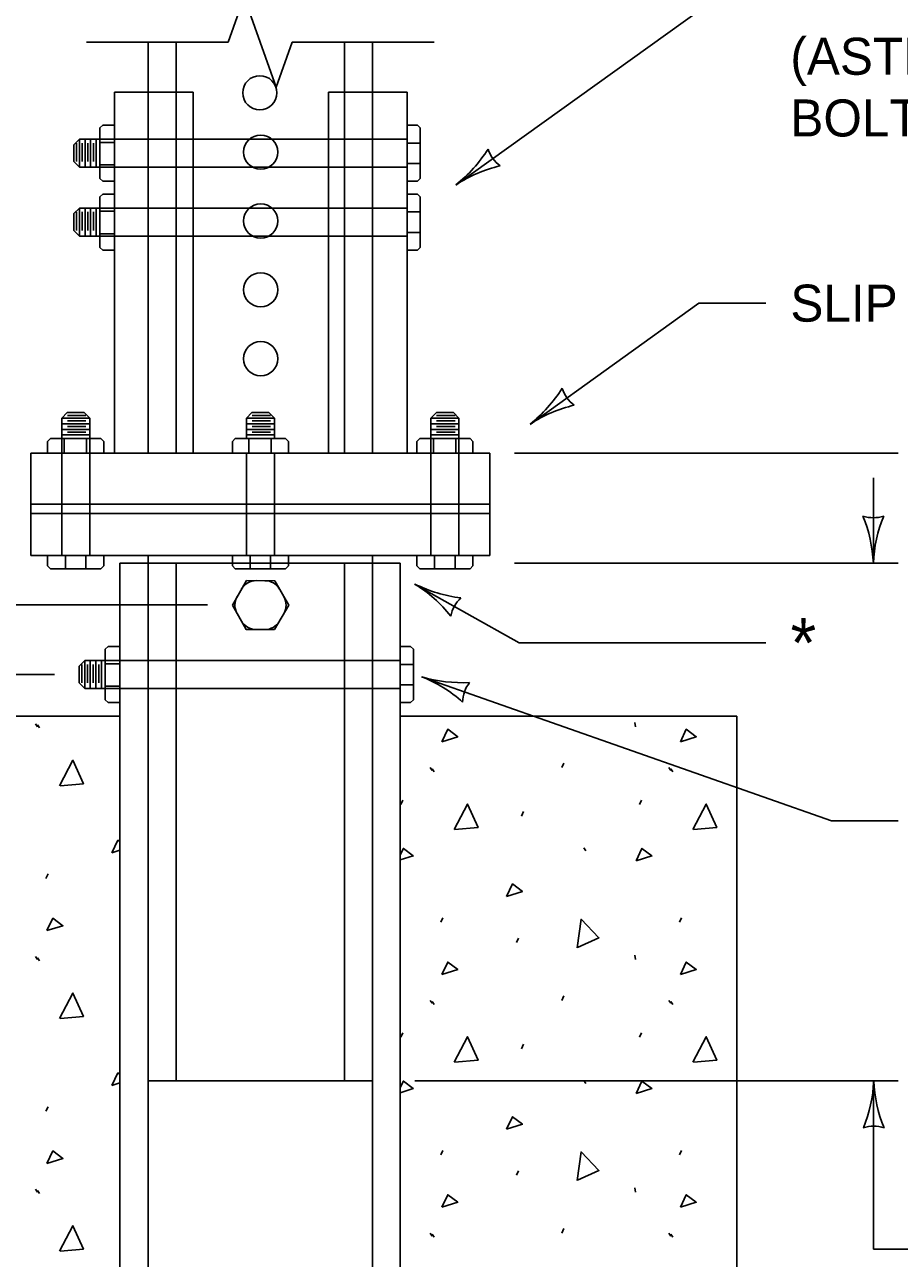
# Model space of a CAD drawing. Extents: x 49940 to 50043, y 49986 to 50011.
# Drawn here: x 50033.246 to 50034.663, y 49992.517 to 49994.516 of the extents above; entities that cross this region are included whole.
import ezdxf

# ---------------------------------------------------------------- set-up
doc = ezdxf.new("R2010")
doc.units = 0
for name, color, linetype in [('Level 1', 7, 'Continuous'), ('Level 2', 7, 'Continuous'), ('Level 3', 7, 'Continuous'), ('Level 4', 7, 'Continuous'), ('Level 6', 7, 'Continuous')]:
    doc.layers.add(name, color=color, linetype=linetype)

msp = doc.modelspace()

# ---------------------------------------------------------------- linework, layer by layer
at = {"layer": 'Level 1'}
for p, q in [((50033.3912, 49994.4061), (50033.3912, 49993.8213)), ((50033.3912, 49994.4061), (50033.5184, 49994.4061)), ((50033.5184, 49994.4061), (50033.5184, 49993.8213)), ((50033.738, 49994.4061), (50033.738, 49993.8213)), ((50033.8652, 49994.4061), (50033.738, 49994.4061)), ((50033.8652, 49994.4061), (50033.8652, 49993.8213)), ((50033.3675, 49994.3484), (50033.3721, 49994.3529)), ((50033.3675, 49994.2666), (50033.3675, 49994.3484)), ((50033.3912, 49994.3529), (50033.3721, 49994.3529)), ((50033.8819, 49994.3529), (50033.8652, 49994.3529)), ((50033.8864, 49994.3484), (50033.8819, 49994.3529)), ((50033.8864, 49994.2666), (50033.8864, 49994.3484)), ((50033.3253, 49994.3211), (50033.3344, 49994.3302)), ((50033.3253, 49994.2939), (50033.3253, 49994.3211)), ((50033.3298, 49994.294), (50033.3298, 49994.3239)), ((50033.3675, 49994.3302), (50033.3344, 49994.3302)), ((50033.3344, 49994.2848), (50033.3344, 49994.3302)), ((50033.3389, 49994.294), (50033.3389, 49994.3239)), ((50033.3435, 49994.2848), (50033.3435, 49994.3302)), ((50033.348, 49994.294), (50033.348, 49994.3239)), ((50033.3525, 49994.2848), (50033.3525, 49994.3302)), ((50033.3571, 49994.294), (50033.3571, 49994.3239)), ((50033.3616, 49994.2848), (50033.3616, 49994.3302)), ((50033.3675, 49994.3249), (50033.3898, 49994.3249)), ((50033.8864, 49994.3239), (50033.8658, 49994.3239)), ((50033.3253, 49994.2939), (50033.3344, 49994.2848)), ((50033.3675, 49994.2848), (50033.3344, 49994.2848)), ((50033.3675, 49994.2887), (50033.3898, 49994.2887)), ((50033.8864, 49994.2908), (50033.8658, 49994.2908)), ((50033.3675, 49994.2666), (50033.3721, 49994.262)), ((50033.3912, 49994.262), (50033.3721, 49994.262)), ((50033.8819, 49994.262), (50033.8652, 49994.262)), ((50033.8819, 49994.262), (50033.8864, 49994.2666)), ((50033.3675, 49994.2367), (50033.3721, 49994.2413)), ((50033.3912, 49994.2413), (50033.3721, 49994.2413)), ((50033.8819, 49994.2413), (50033.8652, 49994.2413)), ((50033.8864, 49994.2367), (50033.8819, 49994.2413)), ((50033.3675, 49994.1549), (50033.3675, 49994.2367)), ((50033.8864, 49994.1549), (50033.8864, 49994.2367)), ((50033.3253, 49994.2095), (50033.3344, 49994.2186)), ((50033.3253, 49994.1822), (50033.3253, 49994.2095)), ((50033.3298, 49994.1824), (50033.3298, 49994.2122)), ((50033.3675, 49994.2186), (50033.3344, 49994.2186)), ((50033.3344, 49994.1731), (50033.3344, 49994.2186)), ((50033.3389, 49994.1824), (50033.3389, 49994.2122)), ((50033.3435, 49994.1731), (50033.3435, 49994.2186)), ((50033.348, 49994.1824), (50033.348, 49994.2122)), ((50033.3525, 49994.1731), (50033.3525, 49994.2186)), ((50033.3571, 49994.1824), (50033.3571, 49994.2122)), ((50033.3616, 49994.1731), (50033.3616, 49994.2186)), ((50033.3675, 49994.2133), (50033.3898, 49994.2133)), ((50033.8864, 49994.2122), (50033.8658, 49994.2122)), ((50033.3253, 49994.1822), (50033.3344, 49994.1731)), ((50033.3675, 49994.1731), (50033.3344, 49994.1731)), ((50033.3675, 49994.177), (50033.3898, 49994.177)), ((50033.8864, 49994.1792), (50033.8658, 49994.1792)), ((50033.3675, 49994.1549), (50033.3721, 49994.1504)), ((50033.3912, 49994.1504), (50033.3721, 49994.1504)), ((50033.8819, 49994.1504), (50033.8652, 49994.1504)), ((50033.8819, 49994.1504), (50033.8864, 49994.1549)), ((50033.3147, 49993.8872), (50033.3056, 49993.8781)), ((50033.3147, 49993.8872), (50033.3419, 49993.8872)), ((50033.3148, 49993.8827), (50033.3447, 49993.8827)), ((50033.3419, 49993.8872), (50033.351, 49993.8781)), ((50033.6139, 49993.8872), (50033.6048, 49993.8781)), ((50033.6139, 49993.8872), (50033.6412, 49993.8872)), ((50033.614, 49993.8827), (50033.6439, 49993.8827)), ((50033.6412, 49993.8872), (50033.6502, 49993.8781)), ((50033.9129, 49993.8872), (50033.9039, 49993.8781)), ((50033.9129, 49993.8872), (50033.9402, 49993.8872)), ((50033.9131, 49993.8827), (50033.9429, 49993.8827)), ((50033.9402, 49993.8872), (50033.9493, 49993.8781)), ((50033.3056, 49993.845), (50033.3056, 49993.8781)), ((50033.3056, 49993.8781), (50033.351, 49993.8781)), ((50033.3056, 49993.869), (50033.351, 49993.869)), ((50033.3148, 49993.8736), (50033.3447, 49993.8736)), ((50033.3148, 49993.8645), (50033.3447, 49993.8645)), ((50033.351, 49993.845), (50033.351, 49993.8781)), ((50033.6048, 49993.845), (50033.6048, 49993.8781)), ((50033.6048, 49993.8781), (50033.6502, 49993.8781)), ((50033.6048, 49993.869), (50033.6502, 49993.869)), ((50033.614, 49993.8736), (50033.6439, 49993.8736)), ((50033.614, 49993.8645), (50033.6439, 49993.8645)), ((50033.6502, 49993.845), (50033.6502, 49993.8781)), ((50033.9039, 49993.845), (50033.9039, 49993.8781)), ((50033.9039, 49993.8781), (50033.9493, 49993.8781)), ((50033.9039, 49993.869), (50033.9493, 49993.869)), ((50033.9131, 49993.8736), (50033.9429, 49993.8736)), ((50033.9131, 49993.8645), (50033.9429, 49993.8645)), ((50033.9493, 49993.845), (50033.9493, 49993.8781)), ((50033.2874, 49993.845), (50033.2829, 49993.8404)), ((50033.2874, 49993.845), (50033.3692, 49993.845)), ((50033.3056, 49993.86), (50033.351, 49993.86)), ((50033.3056, 49993.8509), (50033.351, 49993.8509)), ((50033.3095, 49993.845), (50033.3095, 49993.8227)), ((50033.3148, 49993.8554), (50033.3447, 49993.8554)), ((50033.3457, 49993.845), (50033.3457, 49993.8227)), ((50033.3692, 49993.845), (50033.3738, 49993.8404)), ((50033.5866, 49993.845), (50033.5821, 49993.8404)), ((50033.5866, 49993.845), (50033.6684, 49993.845)), ((50033.6048, 49993.86), (50033.6502, 49993.86)), ((50033.6048, 49993.8509), (50033.6502, 49993.8509)), ((50033.6087, 49993.845), (50033.6087, 49993.8227)), ((50033.614, 49993.8554), (50033.6439, 49993.8554)), ((50033.6449, 49993.845), (50033.6449, 49993.8227)), ((50033.6684, 49993.845), (50033.673, 49993.8404)), ((50033.8857, 49993.845), (50033.8811, 49993.8404)), ((50033.8857, 49993.845), (50033.9675, 49993.845)), ((50033.9039, 49993.86), (50033.9493, 49993.86)), ((50033.9039, 49993.8509), (50033.9493, 49993.8509)), ((50033.9078, 49993.845), (50033.9078, 49993.8227)), ((50033.9131, 49993.8554), (50033.9429, 49993.8554)), ((50033.944, 49993.845), (50033.944, 49993.8227)), ((50033.9675, 49993.845), (50033.972, 49993.8404)), ((50033.2556, 49993.6554), (50033.2556, 49993.8213)), ((50033.2556, 49993.8213), (50033.6048, 49993.8213)), ((50033.2829, 49993.8213), (50033.2829, 49993.8404)), ((50033.3738, 49993.8213), (50033.3738, 49993.8404)), ((50033.5821, 49993.8213), (50033.5821, 49993.8404)), ((50033.6048, 49993.6554), (50033.6048, 49993.8213)), ((50033.6048, 49993.8213), (50033.6502, 49993.8213)), ((50033.6502, 49993.6554), (50033.6502, 49993.8213)), ((50033.6502, 49993.8213), (50033.9993, 49993.8213)), ((50033.673, 49993.8213), (50033.673, 49993.8404)), ((50033.8811, 49993.8213), (50033.8811, 49993.8404)), ((50033.972, 49993.8213), (50033.972, 49993.8404)), ((50033.9993, 49993.6554), (50033.9993, 49993.8213)), ((50033.2556, 49993.7389), (50033.9993, 49993.7389)), ((50033.2556, 49993.7239), (50033.9993, 49993.7239)), ((50033.2556, 49993.6554), (50033.6048, 49993.6554)), ((50033.2829, 49993.6388), (50033.2829, 49993.6554)), ((50033.3116, 49993.6342), (50033.3116, 49993.6548)), ((50033.3447, 49993.6342), (50033.3447, 49993.6548)), ((50033.3738, 49993.6388), (50033.3738, 49993.6554)), ((50033.8542, 49993.6432), (50033.3997, 49993.6432)), ((50033.3997, 49993.6432), (50033.3997, 49990.8091)), ((50033.4457, 49993.6554), (50033.4457, 49993.6432)), ((50033.5821, 49993.6388), (50033.5821, 49993.6554)), ((50033.6048, 49993.6554), (50033.6502, 49993.6554)), ((50033.6109, 49993.6342), (50033.6109, 49993.6548)), ((50033.6439, 49993.6342), (50033.6439, 49993.6548)), ((50033.6502, 49993.6554), (50033.9993, 49993.6554)), ((50033.673, 49993.6388), (50033.673, 49993.6554)), ((50033.8093, 49993.6554), (50033.8093, 49993.6432)), ((50033.8542, 49990.8091), (50033.8542, 49993.6432)), ((50033.8811, 49993.6388), (50033.8811, 49993.6554)), ((50033.9099, 49993.6342), (50033.9099, 49993.6548)), ((50033.9429, 49993.6342), (50033.9429, 49993.6548)), ((50033.972, 49993.6388), (50033.972, 49993.6554)), ((50033.2829, 49993.6388), (50033.2874, 49993.6342)), ((50033.2874, 49993.6342), (50033.3692, 49993.6342)), ((50033.3692, 49993.6342), (50033.3738, 49993.6388)), ((50033.5821, 49993.6388), (50033.5866, 49993.6342)), ((50033.5866, 49993.6342), (50033.6684, 49993.6342)), ((50033.6684, 49993.6342), (50033.673, 49993.6388)), ((50033.8811, 49993.6388), (50033.8857, 49993.6342)), ((50033.8857, 49993.6342), (50033.9675, 49993.6342)), ((50033.9675, 49993.6342), (50033.972, 49993.6388)), ((50033.3762, 49993.5036), (50033.3807, 49993.5082)), ((50033.3762, 49993.4218), (50033.3762, 49993.5036)), ((50033.3997, 49993.5082), (50033.3807, 49993.5082)), ((50033.8708, 49993.5082), (50033.8542, 49993.5082)), ((50033.8542, 49993.5082), (50033.8542, 49993.4173)), ((50033.8754, 49993.5036), (50033.8708, 49993.5082)), ((50033.8754, 49993.4218), (50033.8754, 49993.5036)), ((50033.3338, 49993.4764), (50033.3429, 49993.4855)), ((50033.3762, 49993.4855), (50033.3429, 49993.4855)), ((50033.3429, 49993.44), (50033.3429, 49993.4855)), ((50033.3519, 49993.44), (50033.3519, 49993.4855)), ((50033.361, 49993.44), (50033.361, 49993.4855)), ((50033.3701, 49993.44), (50033.3701, 49993.4855)), ((50033.8542, 49993.4855), (50033.8473, 49993.4855)), ((50033.3338, 49993.4491), (50033.3338, 49993.4764)), ((50033.3383, 49993.4492), (50033.3383, 49993.4791)), ((50033.3474, 49993.4492), (50033.3474, 49993.4791)), ((50033.3565, 49993.4492), (50033.3565, 49993.4791)), ((50033.3656, 49993.4492), (50033.3656, 49993.4791)), ((50033.3762, 49993.4801), (50033.3997, 49993.4801)), ((50033.8754, 49993.4791), (50033.8548, 49993.4791)), ((50033.3338, 49993.4491), (50033.3429, 49993.44)), ((50033.3762, 49993.4439), (50033.3997, 49993.4439)), ((50033.8754, 49993.4461), (50033.8548, 49993.4461)), ((50033.3762, 49993.44), (50033.3429, 49993.44)), ((50033.3762, 49993.4218), (50033.3807, 49993.4173)), ((50033.8708, 49993.4173), (50033.8754, 49993.4218)), ((50033.3997, 49993.4173), (50033.3807, 49993.4173)), ((50033.8708, 49993.4173), (50033.8542, 49993.4173)), ((50033.3997, 49993.3952), (50032.8543, 49993.3952)), ((50033.2632, 49993.3829), (50033.2665, 49993.378)), ((50034.3996, 49993.3952), (50033.8542, 49993.3952)), ((50034.2343, 49993.3853), (50034.2352, 49993.378)), ((50034.3996, 49990.6682), (50034.3996, 49993.3952)), ((50033.2665, 49993.3811), (50033.2697, 49993.3762)), ((50033.9028, 49993.312), (50033.906, 49993.3071)), ((50033.906, 49993.31), (50033.9092, 49993.3052)), ((50034.1158, 49993.312), (50034.1191, 49993.3193)), ((50034.2894, 49993.312), (50034.2926, 49993.3071)), ((50034.2926, 49993.31), (50034.2959, 49993.3052)), ((50033.8551, 49993.2521), (50033.8584, 49993.2594)), ((50034.2419, 49993.2521), (50034.245, 49993.2594)), ((50034.0505, 49993.2335), (50034.0537, 49993.2408)), ((50034.1514, 49993.1818), (50034.1546, 49993.177)), ((50033.2801, 49993.1325), (50033.2835, 49993.1397)), ((50033.9198, 49993.0616), (50033.9229, 49993.0688)), ((50034.3064, 49993.0616), (50034.3096, 49993.0688)), ((50034.0423, 49993.0285), (50034.0457, 49993.0358)), ((50033.2632, 49993.0058), (50033.2665, 49993.001)), ((50033.2665, 49993.004), (50033.2697, 49992.9991)), ((50034.2343, 49993.0082), (50034.2352, 49993.001)), ((50034.1158, 49992.9349), (50034.1191, 49992.9422)), ((50033.9028, 49992.9349), (50033.906, 49992.9301)), ((50033.906, 49992.9331), (50033.9092, 49992.9282)), ((50034.2894, 49992.9349), (50034.2926, 49992.9301)), ((50034.2926, 49992.9331), (50034.2959, 49992.9282)), ((50033.8551, 49992.8751), (50033.8584, 49992.8823)), ((50034.2419, 49992.8751), (50034.245, 49992.8823)), ((50034.0505, 49992.8564), (50034.0537, 49992.8637)), ((50034.1514, 49992.8048), (50034.1546, 49992.7999)), ((50033.2801, 49992.7555), (50033.2835, 49992.7626)), ((50033.9198, 49992.6845), (50033.9229, 49992.6917)), ((50034.3064, 49992.6845), (50034.3096, 49992.6917)), ((50034.0423, 49992.6514), (50034.0457, 49992.6587)), ((50033.2632, 49992.6287), (50033.2665, 49992.6239)), ((50033.2665, 49992.6269), (50033.2697, 49992.6221)), ((50034.2343, 49992.6311), (50034.2352, 49992.6239)), ((50034.1158, 49992.5578), (50034.1191, 49992.5651)), ((50033.9028, 49992.5578), (50033.906, 49992.553)), ((50033.906, 49992.556), (50033.9092, 49992.5512)), ((50034.2894, 49992.5578), (50034.2926, 49992.553)), ((50034.2926, 49992.556), (50034.2959, 49992.5512))]:
    msp.add_line(p, q, dxfattribs=at)
for points in [[(50033.4457, 49994.4875), (50033.4457, 49994.4061)], [(50033.809, 49994.4061), (50033.809, 49994.4875)], [(50033.9213, 49993.3539), (50033.931, 49993.3741), (50033.9472, 49993.362), (50033.9213, 49993.3539)], [(50034.3081, 49993.3539), (50034.3176, 49993.3741), (50034.3338, 49993.362), (50034.3081, 49993.3539)], [(50033.3019, 49993.2826), (50033.3238, 49993.3238), (50033.3407, 49993.2859), (50033.3029, 49993.2826)], [(50033.9414, 49993.2117), (50033.9632, 49993.2529), (50033.9802, 49993.215), (50033.9423, 49993.2117)], [(50034.3282, 49993.2117), (50034.35, 49993.2529), (50034.3668, 49993.215), (50034.329, 49993.2117)], [(50033.3869, 49993.1741), (50033.3966, 49993.1943), (50033.3997, 49993.192)], [(50033.3997, 49993.1781), (50033.3869, 49993.1741)], [(50033.8542, 49993.1706), (50033.8592, 49993.1811), (50033.8752, 49993.169), (50033.8542, 49993.1623)], [(50034.2361, 49993.1609), (50034.2458, 49993.1811), (50034.262, 49993.169), (50034.2361, 49993.1609)], [(50034.0264, 49993.1032), (50034.0361, 49993.1234), (50034.0522, 49993.1112), (50034.0264, 49993.1032)], [(50033.2818, 49993.0478), (50033.2915, 49993.0679), (50033.3077, 49993.0558), (50033.2818, 49993.0478)], [(50034.1406, 49993.0202), (50034.147, 49993.0663), (50034.1759, 49993.0364), (50034.1414, 49993.0203)], [(50033.9213, 49992.9769), (50033.931, 49992.997), (50033.9472, 49992.9849), (50033.9213, 49992.9769)], [(50034.3081, 49992.9769), (50034.3176, 49992.997), (50034.3338, 49992.9849), (50034.3081, 49992.9769)], [(50033.3019, 49992.9057), (50033.3238, 49992.9467), (50033.3407, 49992.9088), (50033.3029, 49992.9057)], [(50033.9414, 49992.8346), (50033.9632, 49992.8758), (50033.9802, 49992.8379), (50033.9423, 49992.8346)], [(50034.3282, 49992.8346), (50034.35, 49992.8758), (50034.3668, 49992.8379), (50034.329, 49992.8346)], [(50033.3869, 49992.797), (50033.3966, 49992.8172), (50033.3997, 49992.8149)], [(50033.8542, 49992.7936), (50033.8592, 49992.804), (50033.8752, 49992.7919), (50033.8542, 49992.7852)], [(50034.2361, 49992.7839), (50034.2458, 49992.804), (50034.262, 49992.7919), (50034.2361, 49992.7839)], [(50033.3997, 49992.801), (50033.3869, 49992.797)], [(50034.0264, 49992.7261), (50034.0361, 49992.7463), (50034.0522, 49992.7342), (50034.0264, 49992.7261)], [(50033.2818, 49992.6707), (50033.2915, 49992.6908), (50033.3077, 49992.6787), (50033.2818, 49992.6707)], [(50034.1406, 49992.6431), (50034.147, 49992.6892), (50034.1759, 49992.6593), (50034.1414, 49992.6434)], [(50033.9213, 49992.5998), (50033.931, 49992.6199), (50033.9472, 49992.6078), (50033.9213, 49992.5998)], [(50034.3081, 49992.5998), (50034.3176, 49992.6199), (50034.3338, 49992.6078), (50034.3081, 49992.5998)], [(50033.3019, 49992.5286), (50033.3238, 49992.5696), (50033.3407, 49992.5318), (50033.3029, 49992.5286)]]:
    msp.add_lwpolyline(points, dxfattribs=at)
msp.add_lwpolyline([(50033.5821, 49993.5754), (50033.6046, 49993.5357), (50033.6502, 49993.5356), (50033.6734, 49993.575), (50033.6507, 49993.6147), (50033.6051, 49993.615)], close=True, dxfattribs=at)
for centre in [(50033.6266, 49994.4053), (50033.6281, 49994.3092), (50033.6281, 49994.3092), (50033.6281, 49994.1977), (50033.6281, 49994.1977), (50033.6281, 49994.1977), (50033.6281, 49994.0861), (50033.6281, 49993.9745)]:
    msp.add_circle(centre, 0.0277, dxfattribs=at)
for centre, start, end in [((50033.6207, 49993.5876), 89.696, 149.6971), ((50033.6348, 49993.5875), 29.6985, 89.6961), ((50033.6135, 49993.5753), 149.6985, 209.6957), ((50033.6419, 49993.5752), 329.6973, 29.6966), ((50033.6205, 49993.563), 209.697, 269.6988), ((50033.6347, 49993.5629), 269.6962, 329.6979)]:
    msp.add_arc(centre, 0.0273, start, end, dxfattribs=at)
at = {"layer": 'Level 3'}
for p, q in [((50034.3744, 49994.5645), (50033.9444, 49994.2558)), ((50034.0645, 49993.8681), (50034.338, 49994.0645)), ((50034.338, 49994.0645), (50034.4462, 49994.0645)), ((50034.0395, 49993.8215), (50034.6609, 49993.8215)), ((50034.6209, 49993.7815), (50034.6209, 49993.6432)), ((50034.6609, 49993.6432), (50034.0395, 49993.6432)), ((50033.8775, 49993.6092), (50034.0468, 49993.5143)), ((50033.5421, 49993.5756), (50032.4723, 49993.5756)), ((50034.0468, 49993.5143), (50034.4462, 49993.5143)), ((50033.2938, 49993.4629), (50032.4723, 49993.4629)), ((50033.8888, 49993.459), (50034.5527, 49993.2255)), ((50034.5527, 49993.2255), (50034.6609, 49993.2255)), ((50033.8777, 49992.8047), (50034.6609, 49992.8047)), ((50034.6209, 49992.8047), (50034.6209, 49992.532)), ((50034.6209, 49992.532), (50034.7291, 49992.532))]:
    msp.add_line(p, q, dxfattribs=at)
for centre, radius, start, end in [((50033.7993, 49994.4385), 0.233, 308.5027, 327.7526), ((50034.0485, 49994.3309), 0.0548, 197.8142, 233.5366), ((50034.0665, 49994.0704), 0.2223, 103.1314, 123.3149), ((50033.9194, 49994.0508), 0.233, 308.5094, 327.7592), ((50034.1686, 49993.9432), 0.0548, 197.8209, 233.5433), ((50034.1866, 49993.6827), 0.2223, 103.1381, 123.3216), ((50034.6206, 49993.7716), 0.0548, 252.1388, 287.8612), ((50034.3879, 49993.6319), 0.233, 2.8273, 22.0772), ((50034.8428, 49993.6342), 0.2223, 157.456, 177.6395), ((50033.7612, 49993.4201), 0.2223, 38.1835, 58.367), ((50033.9816, 49993.818), 0.233, 243.5548, 262.8046), ((50033.9897, 49993.5467), 0.0548, 132.8663, 168.5887), ((50033.8067, 49993.2527), 0.2223, 48.0787, 68.2623), ((50033.9554, 49993.6825), 0.233, 253.45, 272.6999), ((50034.01, 49993.4167), 0.0548, 142.7616, 178.4839), ((50034.3991, 49992.8137), 0.2223, 337.456, 357.6395), ((50034.8539, 49992.816), 0.233, 182.8273, 202.0772), ((50034.6212, 49992.6763), 0.0548, 72.1388, 107.8612)]:
    msp.add_arc(centre, radius, start, end, dxfattribs=at)
at = {"layer": 'Level 4'}
for p, q in [((50033.8652, 49994.3302), (50033.3675, 49994.3302)), ((50033.8652, 49994.2848), (50033.3675, 49994.2848)), ((50033.8652, 49994.2186), (50033.3675, 49994.2186)), ((50033.8652, 49994.1731), (50033.3675, 49994.1731)), ((50033.3056, 49993.6554), (50033.3056, 49993.845)), ((50033.351, 49993.6554), (50033.351, 49993.845)), ((50033.9039, 49993.6554), (50033.9039, 49993.845)), ((50033.9493, 49993.6554), (50033.9493, 49993.845)), ((50033.4457, 49990.8091), (50033.4457, 49993.6432)), ((50033.4912, 49992.8045), (50033.4912, 49993.6432)), ((50033.7637, 49992.8045), (50033.7637, 49993.6432)), ((50033.8093, 49990.8091), (50033.8093, 49993.6432)), ((50033.8542, 49993.4855), (50033.3762, 49993.4855)), ((50033.8542, 49993.44), (50033.3762, 49993.44)), ((50033.4457, 49992.8045), (50033.8093, 49992.8045))]:
    msp.add_line(p, q, dxfattribs=at)
for points in [[(50033.4912, 49994.4875), (50033.4912, 49993.8213)], [(50033.7637, 49993.8213), (50033.7636, 49994.4875)], [(50033.4457, 49994.4061), (50033.4457, 49993.8213)], [(50033.809, 49994.4061), (50033.809, 49993.8213)]]:
    msp.add_lwpolyline(points, dxfattribs=at)
at = {"layer": 'Level 6'}
for p, q in [((50033.6015, 49994.5606), (50033.5756, 49994.4875)), ((50033.6015, 49994.5606), (50033.6274, 49994.4875)), ((50033.3457, 49994.4875), (50033.5756, 49994.4875)), ((50033.6274, 49994.4875), (50033.6533, 49994.4144)), ((50033.6792, 49994.4875), (50033.6533, 49994.4144)), ((50033.6792, 49994.4875), (50033.909, 49994.4875))]:
    msp.add_line(p, q, dxfattribs=at)

# ---------------------------------------------------------------- texts
at = {"layer": 'Level 2'}
for s, p in [('(ASTM F 568M CLASS 4.6)', (50034.4862, 49994.4345)), ('BOLT AND NUT (2 REQURIED)', (50034.4862, 49994.3345)), ('SLIP BASE ASSEMBLY', (50034.4862, 49994.0345))]:
    msp.add_text(s, height=0.06, dxfattribs=at).set_placement(p)
msp.add_text('*', height=0.08, rotation=359.5, dxfattribs=at).set_placement((50034.4859, 49993.4743))

doc.saveas('drawing.dxf')
